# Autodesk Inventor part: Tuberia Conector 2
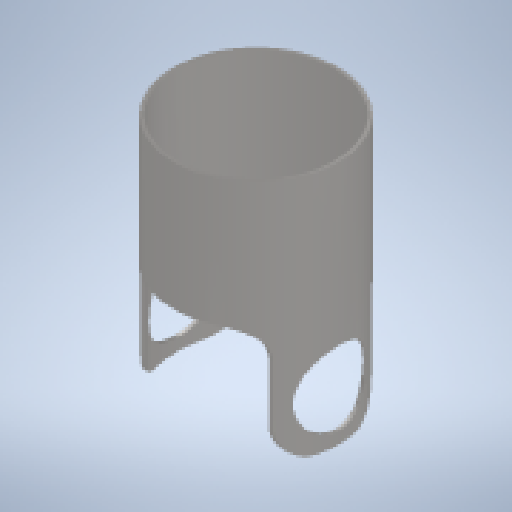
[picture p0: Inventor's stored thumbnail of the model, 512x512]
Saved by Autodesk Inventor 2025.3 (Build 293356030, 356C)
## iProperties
Created: 2025-10
Part Number: Tuberia Conector 2
Material: Hierro, fundido
Document SubType Name: Modeling
Designer: Asus
Density: 7.15 g/cm^3
Appearance: Inoxidable - Bruñido
Author: Asus
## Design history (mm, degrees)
sketch "Boceto1"
  geometry: C1 r 84.138 at (0, 0); C2 r 80.738 at (0, 0); 1 further point
  constraints: 2 centre point, 2 coincident
  dimensions: "d0" = 168.275 diameter of C1; "d1" = 3.4 radial gap between concentric circles of C1 C2
extrude "Extrusión1" new body sketch "Boceto1" distance "d2" = 250; taper "d3" = 0 deg
sketch "Boceto2"
  geometry: L1 (-250, -80.738)-(-250, 80.738) reference; L2 (-250, 84.138)-(-250, -84.138) reference; L3 (-130, 84.138)-(-130, 50); L4 (-130, 50)-(-250, 50); L5 (-250, -50)-(-130, -50); L6 (-130, -50)-(-130, -84.138); L7 (0, 84.138)-(-250, 84.138) reference; L8 (0, -84.138)-(-250, -84.138) reference; L9 (-240, 0)-(40, 0) reference; L10 (-130, 84.138)-(-250, 84.138); L11 (-250, 84.138)-(-250, 50); L12 (-250, 50)-(-130, 50); L13 (-130, 50)-(-130, 84.138); L14 (-250, -50)-(-130, -50); L15 (-130, -50)-(-130, -84.138); L16 (-130, -84.138)-(-250, -84.138); L17 (-250, -84.138)-(-250, -50); 3 further points
  constraints: 24 end point, 5 point on line, 4 parallel, 3 perpendicular, 2 horizontal, 1 vertical
  dimensions: "d4" = 100 distance between parallel lines of L5 L4; "d5" = 50 distance between parallel lines of L9 L4 (= 0.5 x d4); "d6" = 120 distance between parallel lines of L1 L6
extrude "Extrusión2" cut sketch "Boceto2" extent not by distance; stored distance "d7" = 0; taper "d8" = 0 deg
sketch "Boceto3"
  geometry: L1 (-240, 0)-(40, 0) reference; L2 (-250, -50)-(-250, 50) reference; 2 further points
  dimensions: "d9" = 0 distance from line of L1 point (-200, 0); "d10" = 50 distance from line of point (-200, 0) L2
hole "Agujero1" sketch "Boceto3" at (-200, 0) diameter "d11" = 75; stored, may be unused: countersink angle "d15" = 90 deg, drill point angle "d17" = 118 deg; dims "d12" = 6, "d13" = 4, "d14" = 2, "d16" = 8
fillet "Empalme1" dims "d18" = 30
node "Sólido1"
